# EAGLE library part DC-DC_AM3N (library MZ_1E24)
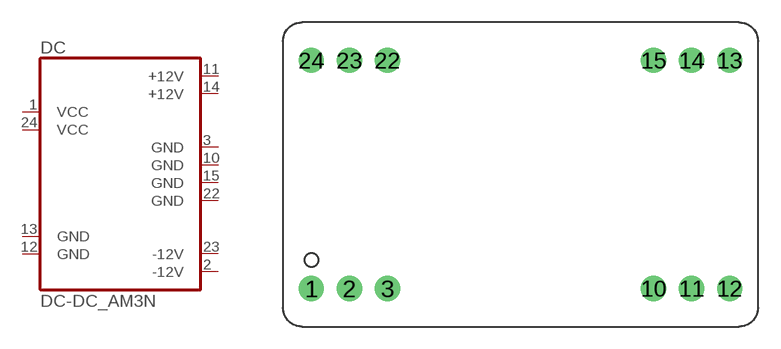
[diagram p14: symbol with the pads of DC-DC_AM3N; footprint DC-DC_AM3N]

Designator prefix DC

## DC-DC_AM3N  [DC-DC_AM3N]
1  VCC  in
2  -12V  pwr
3  GND  pwr
10  GND  pwr
11  +12V  pwr
12  GND  pwr
13  GND  pwr
14  +12V  pwr
15  GND  pwr
22  GND  pwr
23  -12V  pwr
24  VCC  in

## Footprint DC-DC_AM3N (pad centres in mm)
drill 1.016 pad 1.676 round: 1 1.905,2.54; 2 4.445,2.54; 3 6.985,2.54; 10 24.765,2.54; 11 27.305,2.54; 12 29.845,2.54; 13 29.845,17.78; 14 27.305,17.78; 15 24.765,17.78; 22 6.985,17.78; 23 4.445,17.78; 24 1.905,17.78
